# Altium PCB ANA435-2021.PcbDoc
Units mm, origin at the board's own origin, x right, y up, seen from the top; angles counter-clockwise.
Board outline 436.88 x 101.6 mm, 2 copper layers (Top Layer, Bottom Layer); 26 components, 49 nets, 210 pads, 1242 vias.
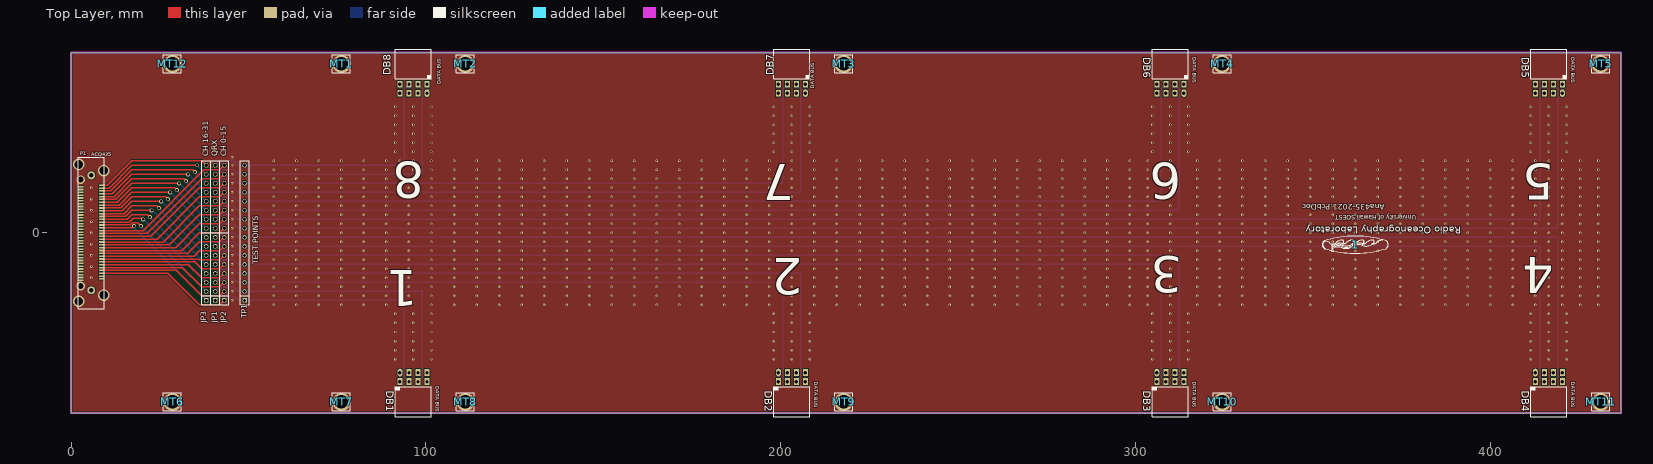
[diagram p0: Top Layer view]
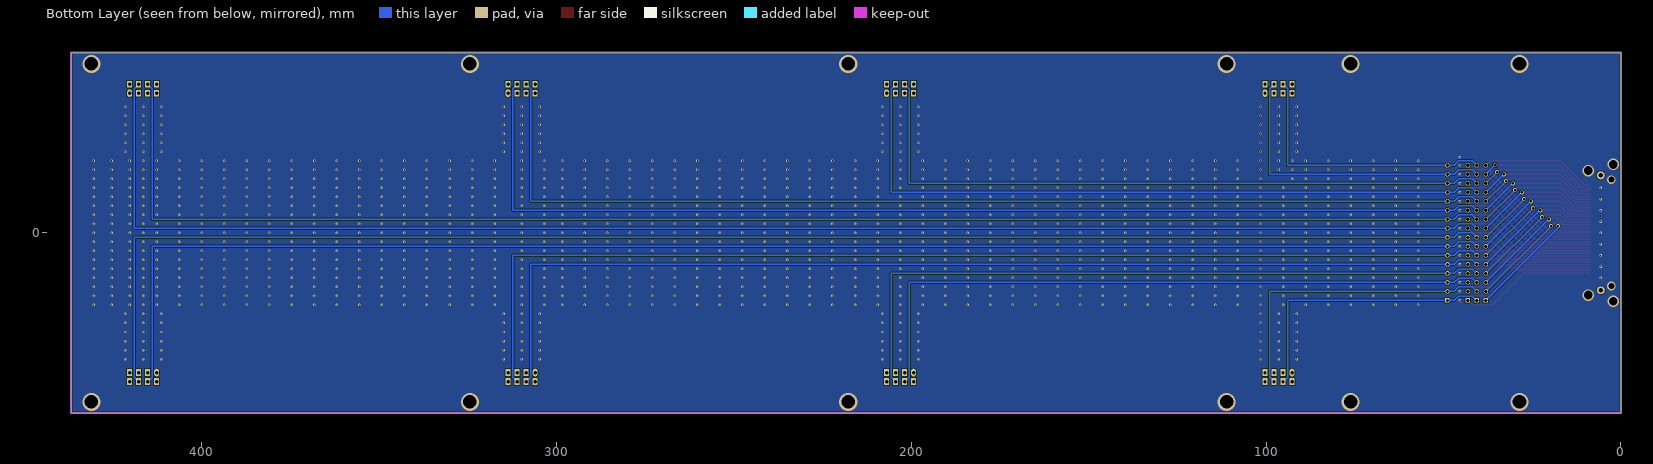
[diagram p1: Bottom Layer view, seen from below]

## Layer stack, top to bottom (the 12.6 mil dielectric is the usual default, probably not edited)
Top Solder: solder mask 0.0102, Solder Resist, Dk 3.5
Top Layer: signal copper 0.0356
Dielectric 1: dielectric 0.32, FR-4, Dk 4.8
Bottom Layer: signal copper 0.0356
Bottom Solder: solder mask 0.0102, Solder Resist, Dk 3.5

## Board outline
0,-50.8 436.88,-50.8 436.88,50.8 0,50.8

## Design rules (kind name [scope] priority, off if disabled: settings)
Clearance [All] p1: gap=0.203 ignorepadtopadclearanceinfootprint=FALSE
HoleSize [All] p1: absolutevalues=TRUE maxlimit=10 minlimit=0.025 maxpercent=80.000 minpercent=20.000
MinimumSolderMaskSliver [All] p1 off: minsoldermaskwidth=0.254
PlaneClearance PlaneClearance_12 [HasPad('MT9-1')] p1: clearance=1.27
PlaneClearance PlaneClearance_11 [HasPad('MT11-1')] p2: clearance=1.27
PlaneClearance PlaneClearance_10 [HasPad('MT5-1')] p3: clearance=1.27
PlaneClearance PlaneClearance_9 [HasPad('MT4-1')] p4: clearance=1.27
PlaneClearance PlaneClearance_8 [HasPad('MT10-1')] p5: clearance=1.27
PlaneClearance PlaneClearance_7 [HasPad('MT3-1')] p6: clearance=1.27
PlaneClearance PlaneClearance_6 [HasPad('MT12-1')] p7: clearance=1.27
PlaneClearance PlaneClearance_5 [HasPad('MT1-1')] p8: clearance=1.27
PlaneClearance PlaneClearance_4 [HasPad('MT2-1')] p9: clearance=1.27
PlaneClearance PlaneClearance_3 [HasPad('MT8-1')] p10: clearance=1.27
PlaneClearance PlaneClearance_2 [HasPad('MT7-1')] p11: clearance=1.27
PlaneClearance PlaneClearance_1 [HasPad('MT6-1')] p12: clearance=1.27
PlaneClearance [All] p13: clearance=0.254
PolygonConnect [All] p1: thpad.connectstyle=Relief thpad.reliefconductorwidth=0.254 thpad.reliefentries=4 thpad.polygonreliefangle="90 Angle" thpad.airgapwidth=0.203 smdpad.connectstyle=Relief smdpad.reliefconductorwidth=0.254 smdpad.reliefentries=4 smdpad.polygonreliefangle="90 Angle" smdpad.airgapwidth=0.203 via.connectstyle=Direct via.reliefconductorwidth=0.254 via.reliefentries=4 via.polygonreliefangle="90 Angle" via.airgapwidth=0.254
RoutingPriority [All] p1: routingpriority=2
RoutingVias [All] p1: holewidth=0.7 width=1.1 viastyle="Through Hole" minholewidth=0.3 minwidth=0.7 maxholewidth=4 maxwidth=7
SilkToSilkClearance [All] p1 off: silktosilkclearance=0.254
SilkToSolderMaskClearance [IsPad] p1 off: minsilkscreentomaskgap=0.254 clearancetoexposedcopper=TRUE
SolderMaskExpansion [All] p1: expansion=0.051
Width [All] p1: maxlimit=10 minlimit=0.254 preferedwidth=0.254 minimp=50.000000 maximp=50.000000 favimp=50.000000
24 further rules are at their usual default settings.

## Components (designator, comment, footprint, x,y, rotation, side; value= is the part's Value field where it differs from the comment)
1 "" LOGOTINY 361.99,-3.328 r180 top
DB1 "DATA BUS" TSW-4X2F 96.52,-40.64 r180 top
DB2 "DATA BUS" TSW-4X2F 203.2,-40.64 r180 top
DB3 "DATA BUS" TSW-4X2F 309.88,-40.64 r180 top
DB4 "DATA BUS" TSW-4X2F 416.56,-40.64 r180 top
DB5 "DATA BUS" TSW-4X2F 416.56,40.64 r0 top
DB6 "DATA BUS" TSW-4X2F 309.88,40.64 r0 top
DB7 "DATA BUS" TSW-4X2F 203.2,40.64 r0 top
DB8 "DATA BUS" TSW-4X2F 96.52,40.64 r0 top
JP1 "QRX" SIP16 40.64,-19.05 r90 top
JP2 "CH 0-15" SIP16 43.18,-19.05 r90 top
JP3 "CH 16-31" SIP16 38.1,-19.05 r90 top
MT1 "GND" MOUNT-3.5 76.2,47.625 r0 top
MT2 "GND" MOUNT-3.5 111.125,47.625 r0 top
MT3 "GND" MOUNT-3.5 217.805,47.625 r0 top
MT4 "GND" MOUNT-3.5 324.485,47.625 r0 top
MT5 "GND" MOUNT-3.5 431.165,47.625 r0 top
MT6 "GND" MOUNT-3.5 28.575,-47.625 r0 top
MT7 "GND" MOUNT-3.5 76.2,-47.625 r0 top
MT8 "GND" MOUNT-3.5 111.125,-47.625 r0 top
MT9 "GND" MOUNT-3.5 217.805,-47.625 r0 top
MT10 "GND" MOUNT-3.5 324.485,-47.625 r0 top
MT11 "GND" MOUNT-3.5 431.165,-47.625 r0 top
MT12 "GND" MOUNT-3.5 28.575,47.625 r0 top
P1 "ACQ435" VHDCI-SMT 5.69,0.025 r270 top
TP1 "TEST POINTS" SIP16 48.895,-19.05 r90 top

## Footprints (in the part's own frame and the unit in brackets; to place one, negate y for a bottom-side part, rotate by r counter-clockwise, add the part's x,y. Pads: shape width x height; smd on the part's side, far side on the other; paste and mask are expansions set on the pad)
LOGOTINY [mm]
  silkscreen extent -9.29,-2.41 9.29,2.41
MOUNT-3.5 [mm]
  round 5.08 on Mech1: 1(0,0)
  silkscreen extent -2.54,-2.54 2.54,2.54
SIP16 [mil]
  rect 50x50 hole 36: 1(0,0)
  round 50 hole 36: 2(100,0) 3(200,0) 4(300,0) 5(400,0) 6(500,0) 7(600,0) 8(700,0) 9(800,0) 10(900,0) 11(1000,0) 12(1100,0) 13(1200,0) 14(1300,0) 15(1400,0) 16(1500,0)
  silkscreen extent -50,-50 1550,50
TSW-4X2F [mil]
  oval 56x85 hole 38: 1(150,-50)
  rect 56x75 hole 38: 2(150,50) 3(50,-50) 4(50,50) 5(-50,-50) 6(-50,50) 7(-150,-50) 8(-150,50)
  silkscreen extent -200,110 200,440
VHDCI-SMT [mm]
  round 2.25 hole 1.2: 0(16.2,0) 0_1(-16.2,0)
  rect 0.45x1.5 smd: 1(13,3) 2(12.2,3) 3(11.4,3) 4(10.6,3) 5(9.8,3) 6(9,3) 7(8.2,3) 8(7.4,3) 9(6.6,3) 10(5.8,3) 11(5,3) 12(4.2,3) 13(3.4,3) 14(2.6,3) 15(1.8,3) 16(1,3) 17(0.2,3) 18(-0.6,3) 19(-1.4,3) 20(-2.2,3) 21(-3,3) 22(-3.8,3) 23(-4.6,3) 24(-5.4,3) 25(-6.2,3) 26(-7,3) 27(-7.8,3) 28(-8.6,3) 29(-9.4,3) 30(-10.2,3) 31(-11,3) 32(-11.8,3) 33(-12.6,3) 34(-13.4,3) 35(13.4,-3) 36(12.6,-3) 37(11.8,-3) 38(11,-3) 39(10.2,-3) 40(9.4,-3) 41(8.6,-3) 42(7.8,-3) 43(7,-3) 44(6.2,-3) 45(5.4,-3) 46(4.6,-3) 47(3.8,-3) 48(3,-3) 49(2.2,-3) 50(1.4,-3) 51(0.6,-3) 52(-0.2,-3) 53(-1,-3) 54(-1.8,-3) 55(-2.6,-3) 56(-3.4,-3) 57(-4.2,-3) 58(-5,-3) 59(-5.8,-3) 60(-6.6,-3) 61(-7.4,-3) 62(-8.2,-3) 63(-9,-3) 64(-9.8,-3) 65(-10.6,-3) 66(-11.4,-3) 67(-12.2,-3) 68(-13,-3)
  silkscreen extent -21.35,-3.73 21.35,3.73

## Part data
DB1 DB2 DB3 DB4 DB5 DB6 DB7 DB8: library part "HEADER 4X2"
JP1 JP2 JP3 TP1: library part "HEADER 16"
MT1 MT2 MT3 MT4 MT5 MT6 MT7 MT8 MT9 MT10 MT11 MT12: library part TP_1
P1: library part MDR68

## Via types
v1: diameter 0.7, hole 0.3, Top Layer to Bottom Layer, 1209 vias
v2: diameter 1.1, hole 0.7, Top Layer to Bottom Layer, 15 vias
v3: diameter 5.08, hole 3.85, Top Layer to Bottom Layer, 12 vias
v4: diameter 3.24, hole 2.44, Top Layer to Bottom Layer, 4 vias
v5: diameter 2.4, hole 1.75, Top Layer to Bottom Layer, 2 vias

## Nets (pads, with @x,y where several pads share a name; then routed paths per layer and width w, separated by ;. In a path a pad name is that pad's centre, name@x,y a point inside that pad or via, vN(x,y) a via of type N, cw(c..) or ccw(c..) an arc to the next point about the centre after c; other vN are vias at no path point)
ADP0: JP2.1 P1.3 | length 38.7
  Top Layer w0.406: P1.3 27.25,-11.375 36.195,-20.32 41.91,-20.32 JP2.1
ADP1: JP2.2 P1.4 | length 38
  Top Layer w0.406: P1.4 29.625,-10.575 36.83,-17.78 41.91,-17.78 JP2.2
ADP2: JP2.3 P1.5 | length 37.3
  Top Layer w0.406: P1.5 31.365,-9.775 36.83,-15.24 41.91,-15.24 JP2.3
ADP3: JP2.4 P1.6 | length 36.6
  Top Layer w0.406: P1.6 33.105,-8.975 36.83,-12.7 41.91,-12.7 JP2.4
ADP4: JP2.5 P1.7 | length 35.8
  Top Layer w0.406: P1.7 34.845,-8.175 36.83,-10.16 41.91,-10.16 JP2.5
ADP5: JP2.6 P1.8 | length 35.1
  Top Layer w0.406: P1.8 35.95,-7.375 36.195,-7.62 41.91,-7.62 JP2.6
ADP6: JP2.7 P1.9 | length 35.6
  Top Layer w0.406: P1.9 34.7,-6.575 36.195,-5.08 41.91,-5.08 JP2.7
ADP7: JP2.8 P1.10 | length 36.4
  Top Layer w0.406: P1.10 32.96,-5.775 36.195,-2.54 41.91,-2.54 JP2.8
ADP8: JP2.9 P1.11 | length 37.1
  Top Layer w0.406: P1.11 31.22,-4.975 36.195,0 41.91,0 JP2.9
ADP9: JP2.10 P1.12 | length 37.8
  Top Layer w0.406: P1.12 29.48,-4.175 36.195,2.54 41.91,2.54 JP2.10
ADP10: JP2.11 P1.13 | length 38.5
  Top Layer w0.406: P1.13 27.74,-3.375 36.195,5.08 41.91,5.08 JP2.11
ADP11: JP2.12 P1.14 | length 39.2
  Top Layer w0.406: P1.14 26,-2.575 36.195,7.62 41.91,7.62 JP2.12
ADP12: JP2.13 P1.15 | length 40
  Top Layer w0.406: P1.15 24.26,-1.775 36.195,10.16 41.91,10.16 JP2.13
ADP13: JP2.14 P1.16 | length 40.7
  Top Layer w0.406: P1.16 22.52,-0.975 36.195,12.7 41.91,12.7 JP2.14
ADP14: JP2.15 P1.17 | length 41.4
  Top Layer w0.406: P1.17 21.415,-0.175 36.83,15.24 41.91,15.24 JP2.15
ADP15: JP2.16 P1.18 | length 42.1
  Top Layer w0.406: P1.18 20.31,0.625 37.465,17.78 41.91,17.78 JP2.16
ADP16: JP3.1 P1.19 | length 39
  Top Layer w0.406: P1.19 17.3,1.425 17.145,1.581 17.469,1.905 v2(17.78,1.905)
  Bottom Layer w0.406: v2(17.78,1.905) 17.78,1.27 JP3.1
ADP17: JP3.2 P1.20 | length 37.7
  Top Layer w0.406: P1.20 16.748,2.225 17.384,2.861 18.176,2.861 18.18,2.857 18.732,2.857 v2(19.685,1.905)
  Bottom Layer w0.406: v2(19.685,1.905) JP3.2
ADP18: JP3.3 P1.21 | length 37.4
  Top Layer w0.406: P1.21 16.36,3.025 17.462,4.127 20.002,4.127 v2(20.32,3.81)
  Bottom Layer w0.406: v2(20.32,3.81) JP3.3
ADP19: JP3.4 P1.22 | length 36.8
  Top Layer w0.406: P1.22 15.89,3.825 17.145,5.08 21.59,5.08 v2(22.225,4.445)
  Bottom Layer w0.406: v2(22.225,4.445) JP3.4
ADP20: JP3.5 P1.23 | length 36.7
  Top Layer w0.406: P1.23 15.42,4.625 17.145,6.35 22.543,6.35 22.701,6.509 v2(22.701,6.35)
  Bottom Layer w0.406: v2(22.701,6.35) 22.86,6.35 JP3.5
ADP21: JP3.6 P1.24 | length 36.1
  Top Layer w0.406: P1.24 14.95,5.425 17.145,7.62 24.13,7.62 v2(24.765,6.985)
  Bottom Layer w0.406: v2(24.765,6.985) JP3.6
ADP22: JP3.7 P1.25 | length 35.8
  Top Layer w0.406: P1.25 14.48,6.225 17.145,8.89 v2(25.4,8.89)
  Bottom Layer w0.406: v2(25.4,8.89) JP3.7
ADP23: JP3.8 P1.26 | length 35.4
  Top Layer w0.406: P1.26 14.01,7.025 17.145,10.16 26.67,10.16 v2(27.305,9.525)
  Bottom Layer w0.406: v2(27.305,9.525) JP3.8
ADP24: JP3.9 P1.27 | length 35.1
  Top Layer w0.406: P1.27 13.54,7.825 17.145,11.43 v2(27.94,11.43)
  Bottom Layer w0.406: v2(27.94,11.43) JP3.9
ADP25: JP3.10 P1.28 | length 34.8
  Top Layer w0.406: P1.28 13.07,8.625 17.145,12.7 29.21,12.7 v2(29.845,12.065)
  Bottom Layer w0.406: v2(29.845,12.065) JP3.10
ADP26: JP3.11 P1.29 | length 34.4
  Top Layer w0.406: P1.29 12.6,9.425 17.145,13.97 v2(30.48,13.97)
  Bottom Layer w0.406: v2(30.48,13.97) JP3.11
ADP27: JP3.12 P1.30 | length 34.1
  Top Layer w0.406: P1.30 12.13,10.225 17.145,15.24 31.75,15.24 v2(32.385,14.605)
  Bottom Layer w0.406: v2(32.385,14.605) JP3.12
ADP28: JP3.13 P1.31 | length 33.8
  Top Layer w0.406: P1.31 11.66,11.025 17.145,16.51 v2(33.02,16.51)
  Bottom Layer w0.406: v2(33.02,16.51) JP3.13
ADP29: JP3.14 P1.32 | length 33.5
  Top Layer w0.406: P1.32 11.19,11.825 17.145,17.78 34.29,17.78 v2(34.925,17.145)
  Bottom Layer w0.406: v2(34.925,17.145) JP3.14
ADP30: JP3.15 P1.33 | length 33.1
  Top Layer w0.406: P1.33 10.72,12.625 17.145,19.05 v2(35.56,19.05)
  Bottom Layer w0.406: v2(35.56,19.05) JP3.15
ADP31: JP3.16 P1.34 | length 32.8
  Top Layer w0.406: P1.34 10.25,13.425 17.145,20.32 36.83,20.32 JP3.16
GND: DB1.1 DB1.2 DB1.3 DB1.5 DB1.7 DB1.8 DB2.1 DB2.2 DB2.3 DB2.5 DB2.7 DB2.8 DB3.1 DB3.2 DB3.3 DB3.5 DB3.7 DB3.8 DB4.1 DB4.2 DB4.3 DB4.5 DB4.7 DB4.8 DB5.1 DB5.2 DB5.3 DB5.5 DB5.7 DB5.8 DB6.1 DB6.2 DB6.3 DB6.5 DB6.7 DB6.8 DB7.1 DB7.2 DB7.3 DB7.5 DB7.7 DB7.8 DB8.1 DB8.2 DB8.3 DB8.5 DB8.7 DB8.8 P1.0 P1.0_1 P1.1 P1.2 P1.35 P1.36 P1.37 P1.38 P1.39 P1.40 P1.41 P1.42 P1.43 P1.44 P1.45 P1.46 P1.47 P1.48 P1.49 P1.50 P1.51 P1.52 P1.53 P1.54 P1.55 P1.56 P1.57 P1.58 P1.59 P1.60 P1.61 P1.62 P1.63 P1.64 P1.65 P1.66 P1.67 P1.68
  other v1: 91.44,-35.56 96.52,-35.56 101.6,-35.56 198.12,-35.56 203.2,-35.56 208.28,-35.56 304.8,-35.56 309.88,-35.56 314.96,-35.56 411.48,-35.56 416.56,-35.56 421.64,-35.56 91.44,-33.02 96.52,-33.02 101.6,-33.02 198.12,-33.02 203.2,-33.02 208.28,-33.02 304.8,-33.02 309.88,-33.02 314.96,-33.02 411.48,-33.02 416.56,-33.02 421.64,-33.02 91.44,-30.48 96.52,-30.48 101.6,-30.48 198.12,-30.48 203.2,-30.48 208.28,-30.48 304.8,-30.48 309.88,-30.48 314.96,-30.48 411.48,-30.48 416.56,-30.48 421.64,-30.48 91.44,-27.94 96.52,-27.94 101.6,-27.94 198.12,-27.94 203.2,-27.94 208.28,-27.94 304.8,-27.94 309.88,-27.94 314.96,-27.94 411.48,-27.94 416.56,-27.94 421.64,-27.94 91.44,-25.4 96.52,-25.4 101.6,-25.4 198.12,-25.4 203.2,-25.4 208.28,-25.4 304.8,-25.4 309.88,-25.4 314.96,-25.4 411.48,-25.4 416.56,-25.4 421.64,-25.4 91.44,-22.86 96.52,-22.86 101.6,-22.86 198.12,-22.86 203.2,-22.86 208.28,-22.86 304.8,-22.86 309.88,-22.86 314.96,-22.86 411.48,-22.86 416.56,-22.86 421.64,-22.86 57.15,-20.32 63.5,-20.32 69.85,-20.32 76.2,-20.32 82.55,-20.32 88.9,-20.32 95.25,-20.32 101.6,-20.32 107.95,-20.32 114.3,-20.32 120.65,-20.32 127,-20.32 133.35,-20.32 139.7,-20.32 146.05,-20.32 152.4,-20.32 158.75,-20.32 165.1,-20.32 171.45,-20.32 177.8,-20.32 184.15,-20.32 190.5,-20.32 196.85,-20.32 203.2,-20.32 209.55,-20.32 215.9,-20.32 222.25,-20.32 228.6,-20.32 234.95,-20.32 241.3,-20.32 247.65,-20.32 254,-20.32 260.35,-20.32 266.7,-20.32 273.05,-20.32 279.4,-20.32 285.75,-20.32 292.1,-20.32 298.45,-20.32 303.53,-20.32 309.88,-20.32 317.5,-20.32 323.85,-20.32 330.2,-20.32 336.55,-20.32 342.9,-20.32 349.25,-20.32 355.6,-20.32 361.95,-20.32 368.3,-20.32 374.65,-20.32 381,-20.32 387.35,-20.32 393.7,-20.32 400.05,-20.32 406.4,-20.32 412.75,-20.32 416.56,-20.32 420.37,-20.32 425.45,-20.32 430.53,-20.32 45.402,-19.05 57.15,-17.78 63.5,-17.78 69.85,-17.78 76.2,-17.78 82.55,-17.78 88.9,-17.78 95.25,-17.78 101.6,-17.78 107.95,-17.78 114.3,-17.78 120.65,-17.78 127,-17.78 133.35,-17.78 139.7,-17.78 146.05,-17.78 152.4,-17.78 158.75,-17.78 165.1,-17.78 171.45,-17.78 177.8,-17.78 184.15,-17.78 190.5,-17.78 196.85,-17.78 203.2,-17.78 209.55,-17.78 215.9,-17.78 222.25,-17.78 228.6,-17.78 234.95,-17.78 241.3,-17.78 247.65,-17.78 254,-17.78 260.35,-17.78 266.7,-17.78 273.05,-17.78 279.4,-17.78 285.75,-17.78 292.1,-17.78 298.45,-17.78 303.53,-17.78 309.88,-17.78 317.5,-17.78 323.85,-17.78 330.2,-17.78 336.55,-17.78 342.9,-17.78 349.25,-17.78 355.6,-17.78 361.95,-17.78 368.3,-17.78 374.65,-17.78 381,-17.78 387.35,-17.78 393.7,-17.78 400.05,-17.78 406.4,-17.78 412.75,-17.78 416.56,-17.78 420.37,-17.78 425.45,-17.78 430.53,-17.78 45.402,-16.51 57.15,-15.24 63.5,-15.24 69.85,-15.24 76.2,-15.24 82.55,-15.24 88.9,-15.24 95.25,-15.24 101.6,-15.24 107.95,-15.24 114.3,-15.24 120.65,-15.24 127,-15.24 133.35,-15.24 139.7,-15.24 146.05,-15.24 152.4,-15.24 158.75,-15.24 165.1,-15.24 171.45,-15.24 177.8,-15.24 184.15,-15.24 190.5,-15.24 196.85,-15.24 203.2,-15.24 209.55,-15.24 215.9,-15.24 222.25,-15.24 228.6,-15.24 234.95,-15.24 241.3,-15.24 247.65,-15.24 254,-15.24 260.35,-15.24 266.7,-15.24 273.05,-15.24 279.4,-15.24 285.75,-15.24 292.1,-15.24 298.45,-15.24 303.53,-15.24 309.88,-15.24 317.5,-15.24 323.85,-15.24 330.2,-15.24 336.55,-15.24 342.9,-15.24 349.25,-15.24 355.6,-15.24 361.95,-15.24 368.3,-15.24 374.65,-15.24 381,-15.24 387.35,-15.24 393.7,-15.24 400.05,-15.24 406.4,-15.24 412.75,-15.24 416.56,-15.24 420.37,-15.24 425.45,-15.24 430.53,-15.24 45.402,-13.97 5.715,-12.7 57.15,-12.7 63.5,-12.7 69.85,-12.7 76.2,-12.7 82.55,-12.7 88.9,-12.7 95.25,-12.7 101.6,-12.7 107.95,-12.7 114.3,-12.7 120.65,-12.7 127,-12.7 133.35,-12.7 139.7,-12.7 146.05,-12.7 152.4,-12.7 158.75,-12.7 165.1,-12.7 171.45,-12.7 177.8,-12.7 184.15,-12.7 190.5,-12.7 196.85,-12.7 203.2,-12.7 209.55,-12.7 215.9,-12.7 222.25,-12.7 228.6,-12.7 234.95,-12.7 241.3,-12.7 247.65,-12.7 254,-12.7 260.35,-12.7 266.7,-12.7 273.05,-12.7 279.4,-12.7 285.75,-12.7 292.1,-12.7 298.45,-12.7 303.53,-12.7 309.88,-12.7 317.5,-12.7 323.85,-12.7 330.2,-12.7 336.55,-12.7 342.9,-12.7 349.25,-12.7 355.6,-12.7 361.95,-12.7 368.3,-12.7 374.65,-12.7 381,-12.7 387.35,-12.7 393.7,-12.7 400.05,-12.7 406.4,-12.7 412.75,-12.7 416.56,-12.7 420.37,-12.7 425.45,-12.7 430.53,-12.7 45.402,-11.43 57.15,-10.16 63.5,-10.16 69.85,-10.16 76.2,-10.16 82.55,-10.16 88.9,-10.16 95.25,-10.16 101.6,-10.16 107.95,-10.16 114.3,-10.16 120.65,-10.16 127,-10.16 133.35,-10.16 139.7,-10.16 146.05,-10.16 152.4,-10.16 158.75,-10.16 165.1,-10.16 171.45,-10.16 177.8,-10.16 184.15,-10.16 190.5,-10.16 196.85,-10.16 203.2,-10.16 209.55,-10.16 215.9,-10.16 222.25,-10.16 228.6,-10.16 234.95,-10.16 241.3,-10.16 247.65,-10.16 254,-10.16 260.35,-10.16 266.7,-10.16 273.05,-10.16 279.4,-10.16 285.75,-10.16 292.1,-10.16 298.45,-10.16 303.53,-10.16 309.88,-10.16 317.5,-10.16 323.85,-10.16 330.2,-10.16 336.55,-10.16 342.9,-10.16 349.25,-10.16 355.6,-10.16 361.95,-10.16 368.3,-10.16 374.65,-10.16 381,-10.16 387.35,-10.16 393.7,-10.16 400.05,-10.16 406.4,-10.16 412.75,-10.16 416.56,-10.16 420.37,-10.16 425.45,-10.16 430.53,-10.16 5.715,-9.525 45.402,-8.89 57.15,-7.62 63.5,-7.62 69.85,-7.62 76.2,-7.62 82.55,-7.62 88.9,-7.62 95.25,-7.62 101.6,-7.62 107.95,-7.62 114.3,-7.62 120.65,-7.62 127,-7.62 133.35,-7.62 139.7,-7.62 146.05,-7.62 152.4,-7.62 158.75,-7.62 165.1,-7.62 171.45,-7.62 177.8,-7.62 184.15,-7.62 190.5,-7.62 196.85,-7.62 203.2,-7.62 209.55,-7.62 215.9,-7.62 222.25,-7.62 228.6,-7.62 234.95,-7.62 241.3,-7.62 247.65,-7.62 254,-7.62 260.35,-7.62 266.7,-7.62 273.05,-7.62 279.4,-7.62 285.75,-7.62 292.1,-7.62 298.45,-7.62 303.53,-7.62 309.88,-7.62 317.5,-7.62 323.85,-7.62 330.2,-7.62 336.55,-7.62 342.9,-7.62 349.25,-7.62 355.6,-7.62 361.95,-7.62 368.3,-7.62 374.65,-7.62 381,-7.62 387.35,-7.62 393.7,-7.62 400.05,-7.62 406.4,-7.62 412.75,-7.62 416.56,-7.62 420.37,-7.62 425.45,-7.62 430.53,-7.62 5.715,-6.35 45.402,-6.35 57.15,-5.08 63.5,-5.08 69.85,-5.08 76.2,-5.08 82.55,-5.08 88.9,-5.08 95.25,-5.08 101.6,-5.08 107.95,-5.08 114.3,-5.08 120.65,-5.08 127,-5.08 133.35,-5.08 139.7,-5.08 146.05,-5.08 152.4,-5.08 158.75,-5.08 165.1,-5.08 171.45,-5.08 177.8,-5.08 184.15,-5.08 190.5,-5.08 196.85,-5.08 203.2,-5.08 209.55,-5.08 215.9,-5.08 222.25,-5.08 228.6,-5.08 234.95,-5.08 241.3,-5.08 247.65,-5.08 254,-5.08 260.35,-5.08 266.7,-5.08 273.05,-5.08 279.4,-5.08 285.75,-5.08 292.1,-5.08 298.45,-5.08 303.53,-5.08 309.88,-5.08 317.5,-5.08 323.85,-5.08 330.2,-5.08 336.55,-5.08 342.9,-5.08 349.25,-5.08 355.6,-5.08 361.95,-5.08 368.3,-5.08 374.65,-5.08 381,-5.08 387.35,-5.08 393.7,-5.08 400.05,-5.08 406.4,-5.08 412.75,-5.08 416.56,-5.08 420.37,-5.08 425.45,-5.08 430.53,-5.08 45.402,-3.81 5.715,-3.175 57.15,-2.54 63.5,-2.54 69.85,-2.54 76.2,-2.54 82.55,-2.54 88.9,-2.54 95.25,-2.54 101.6,-2.54 107.95,-2.54 114.3,-2.54 120.65,-2.54 127,-2.54 133.35,-2.54 139.7,-2.54 146.05,-2.54 152.4,-2.54 158.75,-2.54 165.1,-2.54 171.45,-2.54 177.8,-2.54 184.15,-2.54 190.5,-2.54 196.85,-2.54 203.2,-2.54 209.55,-2.54 215.9,-2.54 222.25,-2.54 228.6,-2.54 234.95,-2.54 241.3,-2.54 247.65,-2.54 254,-2.54 260.35,-2.54 266.7,-2.54 273.05,-2.54 279.4,-2.54 285.75,-2.54 292.1,-2.54 298.45,-2.54 303.53,-2.54 309.88,-2.54 317.5,-2.54 323.85,-2.54 330.2,-2.54 336.55,-2.54 342.9,-2.54 349.25,-2.54 355.6,-2.54 361.95,-2.54 368.3,-2.54 374.65,-2.54 381,-2.54 387.35,-2.54 393.7,-2.54 400.05,-2.54 406.4,-2.54 412.75,-2.54 416.56,-2.54 420.37,-2.54 425.45,-2.54 430.53,-2.54 45.402,-1.27 5.715,0 57.15,0 63.5,0 69.85,0 76.2,0 82.55,0 88.9,0 95.25,0 101.6,0 107.95,0 114.3,0 120.65,0 127,0 133.35,0 139.7,0 146.05,0 152.4,0 158.75,0 165.1,0 171.45,0 177.8,0 184.15,0 190.5,0 196.85,0 203.2,0 209.55,0 215.9,0 222.25,0 228.6,0 234.95,0 241.3,0 247.65,0 254,0 260.35,0 266.7,0 273.05,0 279.4,0 285.75,0 292.1,0 298.45,0 303.53,0 309.88,0 317.5,0 323.85,0 330.2,0 336.55,0 342.9,0 349.25,0 355.6,0 361.95,0 368.3,0 374.65,0 381,0 387.35,0 393.7,0 400.05,0 406.4,0 412.75,0 416.56,0 420.37,0 425.45,0 430.53,0 45.402,1.27 57.15,2.54 63.5,2.54 69.85,2.54 76.2,2.54 82.55,2.54 88.9,2.54 95.25,2.54 101.6,2.54 107.95,2.54 114.3,2.54 120.65,2.54 127,2.54 133.35,2.54 139.7,2.54 146.05,2.54 152.4,2.54 158.75,2.54 165.1,2.54 171.45,2.54 177.8,2.54 184.15,2.54 190.5,2.54 196.85,2.54 203.2,2.54 209.55,2.54 215.9,2.54 222.25,2.54 228.6,2.54 234.95,2.54 241.3,2.54 247.65,2.54 254,2.54 260.35,2.54 266.7,2.54 273.05,2.54 279.4,2.54 285.75,2.54 292.1,2.54 298.45,2.54 303.53,2.54 309.88,2.54 317.5,2.54 323.85,2.54 330.2,2.54 336.55,2.54 342.9,2.54 349.25,2.54 355.6,2.54 361.95,2.54 368.3,2.54 374.65,2.54 381,2.54 387.35,2.54 393.7,2.54 400.05,2.54 406.4,2.54 412.75,2.54 416.56,2.54 420.37,2.54 425.45,2.54 430.53,2.54 5.715,3.175 45.402,3.81 57.15,5.08 63.5,5.08 69.85,5.08 76.2,5.08 82.55,5.08 88.9,5.08 95.25,5.08 101.6,5.08 107.95,5.08 114.3,5.08 120.65,5.08 127,5.08 133.35,5.08 139.7,5.08 146.05,5.08 152.4,5.08 158.75,5.08 165.1,5.08 171.45,5.08 177.8,5.08 184.15,5.08 190.5,5.08 196.85,5.08 203.2,5.08 209.55,5.08 215.9,5.08 222.25,5.08 228.6,5.08 234.95,5.08 241.3,5.08 247.65,5.08 254,5.08 260.35,5.08 266.7,5.08 273.05,5.08 279.4,5.08 285.75,5.08 292.1,5.08 298.45,5.08 303.53,5.08 309.88,5.08 317.5,5.08 323.85,5.08 330.2,5.08 336.55,5.08 342.9,5.08 349.25,5.08 355.6,5.08 361.95,5.08 368.3,5.08 374.65,5.08 381,5.08 387.35,5.08 393.7,5.08 400.05,5.08 406.4,5.08 412.75,5.08 416.56,5.08 420.37,5.08 425.45,5.08 430.53,5.08 5.715,6.35 45.402,6.35 57.15,7.62 63.5,7.62 69.85,7.62 76.2,7.62 82.55,7.62 88.9,7.62 95.25,7.62 101.6,7.62 107.95,7.62 114.3,7.62 120.65,7.62 127,7.62 133.35,7.62 139.7,7.62 146.05,7.62 152.4,7.62 158.75,7.62 165.1,7.62 171.45,7.62 177.8,7.62 184.15,7.62 190.5,7.62 196.85,7.62 203.2,7.62 209.55,7.62 215.9,7.62 222.25,7.62 228.6,7.62 234.95,7.62 241.3,7.62 247.65,7.62 254,7.62 260.35,7.62 266.7,7.62 273.05,7.62 279.4,7.62 285.75,7.62 292.1,7.62 298.45,7.62 303.53,7.62 309.88,7.62 317.5,7.62 323.85,7.62 330.2,7.62 336.55,7.62 342.9,7.62 349.25,7.62 355.6,7.62 361.95,7.62 368.3,7.62 374.65,7.62 381,7.62 387.35,7.62 393.7,7.62 400.05,7.62 406.4,7.62 412.75,7.62 416.56,7.62 420.37,7.62 425.45,7.62 430.53,7.62 45.402,8.89 5.715,9.525 57.15,10.16 63.5,10.16 69.85,10.16 76.2,10.16 82.55,10.16 88.9,10.16 95.25,10.16 101.6,10.16 107.95,10.16 114.3,10.16 120.65,10.16 127,10.16 133.35,10.16 139.7,10.16 146.05,10.16 152.4,10.16 158.75,10.16 165.1,10.16 171.45,10.16 177.8,10.16 184.15,10.16 190.5,10.16 196.85,10.16 203.2,10.16 209.55,10.16 215.9,10.16 222.25,10.16 228.6,10.16 234.95,10.16 241.3,10.16 247.65,10.16 254,10.16 260.35,10.16 266.7,10.16 273.05,10.16 279.4,10.16 285.75,10.16 292.1,10.16 298.45,10.16 303.53,10.16 309.88,10.16 317.5,10.16 323.85,10.16 330.2,10.16 336.55,10.16 342.9,10.16 349.25,10.16 355.6,10.16 361.95,10.16 368.3,10.16 374.65,10.16 381,10.16 387.35,10.16 393.7,10.16 400.05,10.16 406.4,10.16 412.75,10.16 416.56,10.16 420.37,10.16 425.45,10.16 430.53,10.16 45.402,11.43 5.715,12.7 57.15,12.7 63.5,12.7 69.85,12.7 76.2,12.7 82.55,12.7 88.9,12.7 95.25,12.7 101.6,12.7 107.95,12.7 114.3,12.7 120.65,12.7 127,12.7 133.35,12.7 139.7,12.7 146.05,12.7 152.4,12.7 158.75,12.7 165.1,12.7 171.45,12.7 177.8,12.7 184.15,12.7 190.5,12.7 196.85,12.7 203.2,12.7 209.55,12.7 215.9,12.7 222.25,12.7 228.6,12.7 234.95,12.7 241.3,12.7 247.65,12.7 254,12.7 260.35,12.7 266.7,12.7 273.05,12.7 279.4,12.7 285.75,12.7 292.1,12.7 298.45,12.7 303.53,12.7 309.88,12.7 317.5,12.7 323.85,12.7 330.2,12.7 336.55,12.7 342.9,12.7 349.25,12.7 355.6,12.7 361.95,12.7 368.3,12.7 374.65,12.7 381,12.7 387.35,12.7 393.7,12.7 400.05,12.7 406.4,12.7 412.75,12.7 416.56,12.7 420.37,12.7 425.45,12.7 430.53,12.7 45.402,13.97 57.15,15.24 63.5,15.24 69.85,15.24 76.2,15.24 82.55,15.24 88.9,15.24 92.71,15.24 101.6,15.24 107.95,15.24 114.3,15.24 120.65,15.24 127,15.24 133.35,15.24 139.7,15.24 146.05,15.24 152.4,15.24 158.75,15.24 165.1,15.24 171.45,15.24 177.8,15.24 184.15,15.24 190.5,15.24 196.85,15.24 203.2,15.24 209.55,15.24 215.9,15.24 222.25,15.24 228.6,15.24 234.95,15.24 241.3,15.24 247.65,15.24 254,15.24 260.35,15.24 266.7,15.24 273.05,15.24 279.4,15.24 285.75,15.24 292.1,15.24 298.45,15.24 303.53,15.24 309.88,15.24 317.5,15.24 323.85,15.24 330.2,15.24 336.55,15.24 342.9,15.24 349.25,15.24 355.6,15.24 361.95,15.24 368.3,15.24 374.65,15.24 381,15.24 387.35,15.24 393.7,15.24 400.05,15.24 406.4,15.24 412.75,15.24 416.56,15.24 420.37,15.24 425.45,15.24 430.53,15.24 45.402,16.51 57.15,17.78 63.5,17.78 69.85,17.78 76.2,17.78 82.55,17.78 88.9,17.78 92.71,17.78 96.52,17.78 101.6,17.78 107.95,17.78 114.3,17.78 120.65,17.78 127,17.78 133.35,17.78 139.7,17.78 146.05,17.78 152.4,17.78 158.75,17.78 165.1,17.78 171.45,17.78 177.8,17.78 184.15,17.78 190.5,17.78 196.85,17.78 203.2,17.78 209.55,17.78 215.9,17.78 222.25,17.78 228.6,17.78 234.95,17.78 241.3,17.78 247.65,17.78 254,17.78 260.35,17.78 266.7,17.78 273.05,17.78 279.4,17.78 285.75,17.78 292.1,17.78 298.45,17.78 303.53,17.78 309.88,17.78 317.5,17.78 323.85,17.78 330.2,17.78 336.55,17.78 342.9,17.78 349.25,17.78 355.6,17.78 361.95,17.78 368.3,17.78 374.65,17.78 381,17.78 387.35,17.78 393.7,17.78 400.05,17.78 406.4,17.78 412.75,17.78 416.56,17.78 420.37,17.78 425.45,17.78 430.53,17.78 45.402,19.05 57.15,20.32 63.5,20.32 69.85,20.32 76.2,20.32 82.55,20.32 88.9,20.32 92.71,20.32 96.52,20.32 101.6,20.32 107.95,20.32 114.3,20.32 120.65,20.32 127,20.32 133.35,20.32 139.7,20.32 146.05,20.32 152.4,20.32 158.75,20.32 165.1,20.32 171.45,20.32 177.8,20.32 184.15,20.32 190.5,20.32 196.85,20.32 203.2,20.32 209.55,20.32 215.9,20.32 222.25,20.32 228.6,20.32 234.95,20.32 241.3,20.32 247.65,20.32 254,20.32 260.35,20.32 266.7,20.32 273.05,20.32 279.4,20.32 285.75,20.32 292.1,20.32 298.45,20.32 303.53,20.32 309.88,20.32 317.5,20.32 323.85,20.32 330.2,20.32 336.55,20.32 342.9,20.32 349.25,20.32 355.6,20.32 361.95,20.32 368.3,20.32 374.65,20.32 381,20.32 387.35,20.32 393.7,20.32 400.05,20.32 406.4,20.32 412.75,20.32 416.56,20.32 420.37,20.32 425.45,20.32 430.53,20.32 45.402,21.273 91.44,22.86 96.52,22.86 101.6,22.86 198.12,22.86 203.2,22.86 208.28,22.86 304.8,22.86 309.88,22.86 314.96,22.86 411.48,22.86 416.56,22.86 421.64,22.86 91.44,25.4 96.52,25.4 101.6,25.4 198.12,25.4 203.2,25.4 208.28,25.4 304.8,25.4 309.88,25.4 314.96,25.4 411.48,25.4 416.56,25.4 421.64,25.4 91.44,27.94 96.52,27.94 101.6,27.94 198.12,27.94 203.2,27.94 208.28,27.94 304.8,27.94 309.88,27.94 314.96,27.94 411.48,27.94 416.56,27.94 421.64,27.94 91.44,30.48 96.52,30.48 101.6,30.48 198.12,30.48 203.2,30.48 208.28,30.48 304.8,30.48 309.88,30.48 314.96,30.48 411.48,30.48 416.56,30.48 421.64,30.48 91.44,33.02 96.52,33.02 101.6,33.02 198.12,33.02 203.2,33.02 208.28,33.02 304.8,33.02 309.88,33.02 314.96,33.02 411.48,33.02 416.56,33.02 421.64,33.02 91.44,35.56 96.52,35.56 101.6,35.56 198.12,35.56 203.2,35.56 208.28,35.56 304.8,35.56 309.88,35.56 314.96,35.56 411.48,35.56 416.56,35.56 421.64,35.56
  other v3: 28.575,-47.625 76.2,-47.625 111.125,-47.625 217.805,-47.625 324.485,-47.625 431.165,-47.625 28.575,47.625 76.2,47.625 111.125,47.625 217.805,47.625 324.485,47.625 431.165,47.625
  other v4: 2.14,-19.245 9.24,-17.515 9.24,17.565 2.14,19.295
  other v5: 2.69,-14.975 2.69,15.025
I1: DB1.4 JP1.1 TP1.1 | length 77.7
  Bottom Layer w0.4: JP1.1 41.885,-17.805 45.745,-17.805 46.964,-19.024
  Bottom Layer w0.406: 46.964,-19.024 93.98,-19.05 93.98,-40.64 DB1.4
I2: DB2.4 JP1.3 TP1.3 | length 189.5
  Bottom Layer w0.4: JP1.3 41.885,-12.725 45.745,-12.725 46.964,-13.944 ; TP1.3 200.6,-13.97 200.66,-14.03
  Bottom Layer w0.406: 46.964,-13.944 TP1.3@48.895,-13.945 ; 200.66,-14.03 200.66,-40.64 DB2.4
I3: DB3.4 JP1.5 TP1.5 | length 301.3
  Bottom Layer w0.4: JP1.5 41.885,-7.645 45.745,-7.645 46.964,-8.864 ; TP1.5 307.34,-8.89
  Bottom Layer w0.406: 46.964,-8.864 TP1.5@48.895,-8.865 ; 307.34,-8.89 307.34,-40.64 DB3.4
I4: DB4.4 JP1.7 TP1.7 | length 413.2
  Bottom Layer w0.4: JP1.7 41.885,-2.565 45.745,-2.565 46.964,-3.784
  Bottom Layer w0.406: 46.964,-3.784 48.895,-3.785 TP1.7@49.04,-3.639 ; TP1.7 414.02,-3.81 414.02,-40.64 DB4.4
I5: DB5.4 JP1.9 TP1.9 | length 420.9
  Bottom Layer w0.4: JP1.9 41.885,2.515 45.745,2.515 46.964,1.296 ; TP1.9 419.1,1.27
  Bottom Layer w0.406: 46.964,1.296 48.895,1.295 TP1.9@49.04,1.44 ; DB5.4 419.1,40.64 419.1,1.27
I6: DB6.4 JP1.11 TP1.11 | length 308.9
  Bottom Layer w0.4: JP1.11 41.885,7.595 45.745,7.595 46.964,6.376 ; TP1.11 312.42,6.35
  Bottom Layer w0.406: 46.964,6.376 TP1.11@48.895,6.375 ; DB6.4 312.42,40.64 312.42,6.35
I7: DB7.4 JP1.13 TP1.13 | length 197.1
  Bottom Layer w0.4: JP1.13 41.885,12.675 45.745,12.675 46.99,11.43 205.74,11.43
  Bottom Layer w0.406: DB7.4 205.74,40.64 205.74,11.43
I8: DB8.4 JP1.15 TP1.15 | length 85.4
  Bottom Layer w0.4: JP1.15 41.885,17.755 45.745,17.755 46.964,16.536
  Bottom Layer w0.406: 46.964,16.536 48.895,16.535 48.92,16.511 99.059,16.511 99.06,40.64 DB8.4
Q1: DB1.6 JP1.2 TP1.2 | length 85.4
  Bottom Layer w0.406: JP1.2 41.91,-15.24 45.72,-15.24 46.99,-16.51 TP1.2 99.06,-16.51 99.06,-40.64 DB1.6
Q2: DB2.6 JP1.4 TP1.4 | length 197.1
  Bottom Layer w0.4: JP1.4 41.885,-10.185 45.745,-10.185 46.964,-11.404
  Bottom Layer w0.406: 46.964,-11.404 TP1.4@48.895,-11.405 ; TP1.4 205.677,-11.43 205.74,-11.493 205.74,-40.64 DB2.6
Q3: DB3.6 JP1.6 TP1.6 | length 308.9
  Bottom Layer w0.4: JP1.6 41.885,-5.105 45.745,-5.105 46.964,-6.324 ; TP1.6 312.42,-6.35
  Bottom Layer w0.406: 46.964,-6.324 TP1.6@48.895,-6.325 ; DB3.6 312.42,-40.64 312.42,-6.35
Q4: DB4.6 JP1.8 TP1.8 | length 420.6
  Bottom Layer w0.4: JP1.8 41.885,-0.025 45.745,-0.025 46.964,-1.244
  Bottom Layer w0.406: 46.964,-1.244 TP1.8@48.895,-1.245 ; TP1.8 419.1,-1.27 419.1,-40.64 DB4.6
Q5: DB5.6 JP1.10 TP1.10 | length 413.2
  Bottom Layer w0.4: JP1.10 41.885,5.055 45.745,5.055 46.964,3.836 ; TP1.10 414.02,3.81
  Bottom Layer w0.406: 46.964,3.836 48.895,3.835 TP1.10@49.04,3.981 ; 414.02,3.81 414.02,40.64 DB5.6
Q6: DB6.6 JP1.12 TP1.12 | length 301.3
  Bottom Layer w0.4: JP1.12 41.885,10.135 45.745,10.135 46.964,8.916
  Bottom Layer w0.406: 46.964,8.916 TP1.12@48.895,8.915 ; TP1.12 307.34,8.89 307.34,40.64 DB6.6
Q7: DB7.6 JP1.14 TP1.14 | length 189.5
  Bottom Layer w0.4: JP1.14 41.885,15.215 45.745,15.215 46.964,13.996 ; TP1.14 200.66,13.97
  Bottom Layer w0.406: 46.964,13.996 TP1.14@48.895,13.995 ; 200.66,13.97 200.66,40.64 DB7.6
Q8: DB8.6 JP1.16 TP1.16 | length 77.7
  Bottom Layer w0.4: JP1.16 41.885,20.295 45.745,20.295 46.964,19.076
  Bottom Layer w0.406: 46.964,19.076 93.98,19.05 93.98,40.64 DB8.6
pads on no net: MT1.1 MT2.1 MT3.1 MT4.1 MT5.1 MT6.1 MT7.1 MT8.1 MT9.1 MT10.1 MT11.1 MT12.1

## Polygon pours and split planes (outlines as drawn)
GND on Top Layer "Bottom Layer-No Net" (solid, remove dead copper, pour order 0): -4.298,54.219 -4.298,-54.952 -4.543,-55.196 439.225,-55.196 439.469,-54.952 439.469,51.044 441.667,53.242
GND on Bottom Layer "Bottom Layer-No Net" (solid, remove dead copper, pour order 2): -4.298,54.219 -4.298,-54.952 -4.543,-55.196 439.225,-55.196 439.469,-54.952 439.469,51.044 441.667,53.242

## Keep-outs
Keep-Out Layer:
  the board outline again, w0.61

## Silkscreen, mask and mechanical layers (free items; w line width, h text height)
Top Overlay:
  lines w0.305: 36.83,0 44.45,0
  text "8" at 99.5,20.027 h10.16 r180
  text "6" at 312.957,19.783 h10.16 r180
  text "5" at 417.977,19.538 h10.16 r180
  text "7" at 203.786,19.294 h10.16 r180
  text "Ana435-2021.PcbDoc" at 370.245,8.102 h1.52 r180
  text "University of Hawaii SOEST" at 379.135,4.927 h1.27 r180
  text "Radio Oceanography Laboratory" at 391.835,1.752 h1.91 r180
  text "3" at 313.202,-6.594 h10.16 r180
  text "4" at 417.977,-6.838 h10.16 r180
  text "2" at 206.229,-7.083 h10.16 r180
  text "1" at 97.79,-10.502 h10.16 r180
Bottom Solder:
  rectangle: 0,-50.165 10.16,-31.75
  rectangle: 0.635,31.75 8.89,50.165
  rectangle: 0.635,35.56 8.89,38.1
  lines w1.27: 0.635,-34.925 0.635,34.925
  lines w6.35: 3.175,-47.625 433.705,-47.625 433.705,47.625 3.175,47.625
Mechanical 1:
  circle w0.254: c0,0 r1.27
  rectangle: 373.38,-67.31 388.62,-62.23
  rectangle: 411.48,-67.31 421.64,-62.23
  rectangle: 449.58,-67.31 459.74,-62.23
  rectangle: 365.76,-65.405 467.36,-62.23
  rectangle: 160.02,-67.31 175.26,-62.23
  rectangle: 198.12,-67.31 208.28,-62.23
  rectangle: 236.22,-67.31 246.38,-62.23
  rectangle: 45.72,-65.405 147.32,-62.23
  rectangle: 129.54,-67.31 139.7,-62.23
  rectangle: 91.44,-67.31 101.6,-62.23
  rectangle: 53.34,-67.31 68.58,-62.23
  rectangle: 266.7,-67.31 281.94,-62.23
  rectangle: 304.8,-67.31 314.96,-62.23
  rectangle: 342.9,-67.31 353.06,-62.23
  rectangle: 259.08,-65.405 360.68,-62.23
  rectangle: 365.76,57.15 467.36,60.325
  rectangle: 373.38,57.15 383.54,62.23
  rectangle: 411.48,57.15 421.64,62.23
  rectangle: 444.5,57.15 459.74,62.23
  rectangle: 337.82,57.15 353.06,62.23
  rectangle: 304.8,57.15 314.96,62.23
  rectangle: 266.7,57.15 276.86,62.23
  rectangle: 259.08,57.15 360.68,60.325
  rectangle: 152.4,57.15 254,60.325
  rectangle: 160.02,57.15 170.18,62.23
  rectangle: 198.12,57.15 208.28,62.23
  rectangle: 231.14,57.15 246.38,62.23
  rectangle: 124.46,57.15 139.7,62.23
  rectangle: 91.44,57.15 101.6,62.23
  rectangle: 53.34,57.15 63.5,62.23
  rectangle: 45.72,57.15 147.32,60.325
  rectangle: 152.4,-65.405 254,-62.23
  lines w0.203: 111.125,-78.74 111.125,60.96 ; 217.805,-76.2 217.805,68.58 ; 431.165,-68.58 431.165,57.15 ; 416.56,-68.58 416.56,-36.83 416.56,-68.58
  lines w0.254: -3.81,0 3.175,0 ; 437.515,-58.42 437.515,-50.165 ; 437.515,50.165 437.515,64.135
  lines w0.305: 437.388,-50.292 458.978,-50.292 ; 437.388,50.038 460.248,50.038
  text "Q I" at 88.9,58.42 h4.06
  text "Q I" at 198.12,55.88 h4.06
  text "Q I" at 414.02,55.88 h4.06
  text "Q I" at 304.8,53.34 h5.08
  text "0.8mm" at 6.3,14.2 h1
  text "I Q" at 91.44,-58.42 h4.06
  text "I Q" at 195.58,-58.42 h4.06
  text "I Q" at 302.26,-58.42 h4.06
Mechanical 2:
  lines w0.152: 58.42,-43.18 58.42,42.545
  lines w0.203: 50.8,-53.34 50.8,53.34
  lines w0.254: 27.94,-47.625 29.21,-47.625 ; 28.575,-48.26 28.575,-46.99 ; 75.565,-47.625 76.835,-47.625 ; 76.2,-48.26 76.2,-46.99 ; 53.34,-52.07 68.58,-52.07 68.58,-43.18 53.34,-43.18 53.34,-52.07 ; 53.34,43.18 63.5,43.18 63.5,52.07 53.34,52.07 53.34,43.18
  text "Samtec SSW-104-02-L-D-RA" at 55.88,73.66 h3.81
  text "E:\__PROJECT\_PIERREFLAMENT\__LERA4P\ANA_BACK\GERBER\" at 12.7,66.04 h3.81
  text "ANA-SMT1.DSN" at 212.725,66.04 h3.81
  text "M-3.5 MOUNTING HOLES (3.85mm) 03/16/2017)" at 263.525,66.04 h5.08
  text "<<== L.O. BOARD" at 50.8,53.34 h4.57
  text "VHDCI-SMT" at -19.304,47.117 h10 r270
  text "DIGIKEY   WM7304-ND" at -5.715,37.465 h3.81 r270
  text "Q8" at 45.72,18.415 h1.02
  text "I8" at 45.72,15.875 h1.02
  text "Q7" at 45.72,13.335 h1.02
  text "A31" at 10.795,12.7 h1.02
  text "I7" at 45.72,10.795 h1.02
  text "Q6" at 45.72,8.255 h1.02
  text "A25" at 10.16,7.62 h1.02
  text "I6" at 45.72,5.715 h1.02
  text "Q5" at 45.72,3.175 h1.02
  text "I5" at 45.72,0.635 h1.02
  text "Q4" at 45.72,-1.905 h1.02
  text "I4" at 45.72,-4.445 h1.02
  text "Q3" at 45.72,-6.985 h1.02
  text "A8" at 10.795,-8.89 h1.02
  text "I3" at 45.72,-9.525 h1.02
  text "Q2" at 45.72,-12.065 h1.02
  text "A1" at 10.795,-13.335 h1.02
  text "I2" at 45.72,-14.605 h1.02
  text "Q1" at 45.72,-17.145 h1.02
  text "I1" at 45.72,-19.685 h1.02
  text "1125mil,-1875mil" at 19.685,-53.34 h1.52
  text "3000mil,-1875mil" at 67.31,-53.34 h1.52
  text "REV 09/09/2016" at 58.42,-58.42 h3.81
  text "GERBER 09/09/2016" at 117.475,-58.42 h3.81
  text "DRC 09/09/2016" at 194.945,-58.42 h3.81
  text "ANA-BP10.NET" at 250.825,-58.42 h3.81
  text "PNP 09/09/2016" at 57.785,-73.025 h3.81
  text "DRL 09/09/2016" at 116.84,-73.025 h3.81
  text "XLN 09/09/2016" at 173.99,-73.025 h3.81
  text "SAVE GROUND FILLS" at 249.555,-76.835 h10.16
  text "MEXICO PRODUCTION" at 66.675,-100.33 h19.05
Mechanical 5:
  lines w0.127: 299.672,-237.813 299.672,-229.133 ; 338.78,-222.308 456.082,-222.308 ; 338.78,-215.483 456.082,-215.483 ; 338.78,-204.393 456.082,-204.393 ; 338.78,-200.127 456.082,-200.127 ; 338.78,-195.861 456.082,-195.861 ; 338.78,-191.596 456.082,-191.596 ; 362.155,-208.658 362.155,-187.33 ; 379.653,-229.133 379.653,-208.658 ; 419.851,-208.658 419.851,-187.33 ; 438.873,-208.658 438.873,-187.33 ; 456.082,-187.33 299.672,-187.33 ; 299.672,-229.133 299.672,-187.33 ; 299.672,-229.133 338.78,-229.133 ; 299.672,-229.133 456.082,-229.133 ; 299.672,-187.33 338.78,-187.33 ; 338.78,-229.133 338.78,-208.658 ; 338.78,-229.133 456.082,-229.133 ; 338.78,-229.133 338.78,-187.33 ; 338.78,-229.133 338.78,-187.33 ; 338.78,-208.658 456.082,-208.658 ; 338.78,-208.658 456.082,-208.658 ; 438.015,-229.133 438.015,-215.483 ; 438.015,-229.133 456.082,-229.133 ; 438.015,-229.133 438.015,-215.483 ; 438.015,-222.308 438.015,-215.483 ; 438.015,-222.308 456.082,-222.308 ; 438.015,-222.308 438.015,-215.483 ; 438.015,-215.483 456.082,-215.483 ; 438.015,-215.483 456.082,-215.483 ; 456.082,-229.133 456.082,-208.658 ; 456.082,-229.133 456.082,-215.483 ; 456.082,-222.308 456.082,-215.483
  lines w0.5: -27.745,-237.802 -27.745,145.073 456.092,145.073 456.092,-237.802 299.692,-237.802 -27.745,-237.802
  text "Radio / Oceanography / Laboratory" at 305.619,-201.92 h4
  text "Indice" at 342.841,-207.248 h1.76
  text "Modification" at 381.81,-207.248 h1.76
  text "Date" at 425.484,-207.248 h1.76
  text "Dessine par" at 441.038,-207.331 h1.5
  text "Edition" at 339.75,-213.26 h1.76
  text ":" at 359.689,-213.26 h1.76
  text "CARTE ANNA435-2021" at 383.492,-213.902 h1.8
  text "Dessinateur" at 339.75,-219.271 h1.76
  text "Folio" at 438.89,-219.271 h1.8
  text ":" at 359.689,-219.292 h1.76
  text ":" at 447.359,-219.292 h1.76
  text "1/1" at 449.736,-219.668 h1.76
  text "RONVEL" at 362.757,-219.783 h1.95
  text ":" at 359.689,-225.885 h1.76
  text "Date" at 339.75,-225.936 h1.76
  text "Ind" at 438.89,-225.936 h1.95
  text "03-04-21" at 361.792,-226.902 h1.8
Mechanical 7:
  text "PLAN DE CABLAGE" at 387.492,-220.402 h4
Mechanical 9:
  text "PLAN DE PERCAGE" at 393.092,-220.302 h4
Drill Drawing:
  circle w0.254: c35.737,-106.219 r0.593
  circle w0.254: c35.737,-106.219 r0.988
  circle w0.254: c35.737,-115.113 r0.988
  lines w0.254: 34.749,-132.901 35.737,-133.89 36.725,-132.901 35.737,-131.913 34.749,-132.901 ; 34.749,-128.948 35.243,-128.948 35.737,-129.443 36.231,-128.948 36.725,-128.948 36.231,-128.454 36.725,-127.96 36.231,-127.96 35.737,-127.466 35.243,-127.96 34.749,-127.96 35.243,-128.454 34.749,-128.948 ; 34.749,-123.019 36.725,-123.019 35.737,-124.996 34.749,-123.019 ; 34.749,-118.572 36.725,-118.572 35.737,-120.549 34.749,-118.572 ; 34.749,-111.655 36.725,-111.655 36.725,-109.678 34.749,-109.678 34.749,-111.655 ; 34.749,-102.266 35.243,-102.266 35.243,-102.761 36.231,-102.761 36.231,-102.266 36.725,-102.266 36.725,-101.278 36.231,-101.278 36.231,-100.784 35.243,-100.784 35.243,-101.278 34.749,-101.278 34.749,-102.266 ; 35.144,-118.967 36.33,-118.967 35.737,-120.153 35.144,-118.967 ; 35.144,-111.259 36.33,-111.259 36.33,-110.073 35.144,-110.073 35.144,-111.259
  lines w0.381: 32.989,-135.224 352.073,-135.224 ; 32.989,-99.648 352.073,-99.648 ; 49.185,-139.671 49.185,-95.201 ; 68.365,-139.671 68.365,-95.201 ; 102.66,-139.671 102.66,-95.201 ; 117.522,-139.671 117.522,-95.201 ; 139.141,-139.671 139.141,-95.201 ; 183.513,-139.671 183.513,-95.201 ; 200.864,-139.671 200.864,-95.201 ; 222.839,-139.671 222.839,-95.201 ; 246.761,-139.671 246.761,-95.201 ; 271.936,-139.671 271.936,-95.201 ; 311.337,-139.671 311.337,-95.201 ; 32.989,-139.671 352.073,-139.671 352.073,-95.201 32.989,-95.201 32.989,-139.671
  text "Symbol" at 35.657,-98.314 h2.13
  text "Count" at 50.519,-98.314 h2.13
  text "Hole Size" at 69.699,-98.314 h2.13
  text "Plated" at 103.995,-98.314 h2.13
  text "Hole Type" at 118.856,-98.314 h2.13
  text "Drill Layer Pair" at 140.475,-98.314 h2.13
  text "Via/Pad" at 184.847,-98.314 h2.13
  text "Pad Shape" at 202.198,-98.314 h2.13
  text "Template" at 224.173,-98.314 h2.13
  text "Description" at 248.095,-98.314 h2.13
  text "Hole Tolerance (+)" at 273.27,-98.314 h2.13
  text "Hole Tolerance (-)" at 312.671,-98.314 h2.13
  text "2" at 50.519,-102.761 h1.78
  text "1,200mm (47,24mil)" at 69.699,-102.761 h1.78
  text "PTH" at 103.995,-102.761 h1.78
  text "Round" at 118.856,-102.761 h1.78
  text "Top Layer - Bottom Layer" at 140.475,-102.761 h1.78
  text "Pad" at 184.847,-102.761 h1.78
  text "Rounded" at 202.198,-102.761 h1.78
  text "c225h120" at 224.173,-102.761 h1.78
  text "2" at 50.519,-107.208 h1.78
  text "1,750mm (68,90mil)" at 69.699,-107.208 h1.78
  text "PTH" at 103.995,-107.208 h1.78
  text "Round" at 118.856,-107.208 h1.78
  text "Top Layer - Bottom Layer" at 140.475,-107.208 h1.78
  text "Via" at 184.847,-107.208 h1.78
  text "Rounded" at 202.198,-107.208 h1.78
  text "v240h175" at 224.173,-107.208 h1.78
  text "4" at 50.519,-111.655 h1.78
  text "2,440mm (96,06mil)" at 69.699,-111.655 h1.78
  text "PTH" at 103.995,-111.655 h1.78
  text "Round" at 118.856,-111.655 h1.78
  text "Top Layer - Bottom Layer" at 140.475,-111.655 h1.78
  text "Via" at 184.847,-111.655 h1.78
  text "Rounded" at 202.198,-111.655 h1.78
  text "v324h244" at 224.173,-111.655 h1.78
  text "12" at 50.519,-116.102 h1.78
  text "3,850mm (151,58mil)" at 69.699,-116.102 h1.78
  text "PTH" at 103.995,-116.102 h1.78
  text "Round" at 118.856,-116.102 h1.78
  text "Top Layer - Bottom Layer" at 140.475,-116.102 h1.78
  text "Via" at 184.847,-116.102 h1.78
  text "Rounded" at 202.198,-116.102 h1.78
  text "v508h385m473" at 224.173,-116.102 h1.78
  text "15" at 50.519,-120.549 h1.78
  text "0,700mm (27,56mil)" at 69.699,-120.549 h1.78
  text "PTH" at 103.995,-120.549 h1.78
  text "Round" at 118.856,-120.549 h1.78
  text "Top Layer - Bottom Layer" at 140.475,-120.549 h1.78
  text "Via" at 184.847,-120.549 h1.78
  text "Rounded" at 202.198,-120.549 h1.78
  text "v110h70m55" at 224.173,-120.549 h1.78
  text "64" at 50.519,-124.996 h1.78
  text "0,914mm (36,00mil)" at 69.699,-124.996 h1.78
  text "PTH" at 103.995,-124.996 h1.78
  text "Round" at 118.856,-124.996 h1.78
  text "Top Layer - Bottom Layer" at 140.475,-124.996 h1.78
  text "Pad" at 184.847,-124.996 h1.78
  text "(Mixed)" at 202.198,-124.996 h1.78
  text "(Mixed)" at 224.173,-124.996 h1.78
  text "64" at 50.519,-129.443 h1.78
  text "0,965mm (38,00mil)" at 69.699,-129.443 h1.78
  text "PTH" at 103.995,-129.443 h1.78
  text "Round" at 118.856,-129.443 h1.78
  text "Top Layer - Bottom Layer" at 140.475,-129.443 h1.78
  text "Pad" at 184.847,-129.443 h1.78
  text "(Mixed)" at 202.198,-129.443 h1.78
  text "(Mixed)" at 224.173,-129.443 h1.78
  text "1209" at 50.519,-133.89 h1.78
  text "0,300mm (11,81mil)" at 69.699,-133.89 h1.78
  text "PTH" at 103.995,-133.89 h1.78
  text "Round" at 118.856,-133.89 h1.78
  text "Top Layer - Bottom Layer" at 140.475,-133.89 h1.78
  text "Via" at 184.847,-133.89 h1.78
  text "Rounded" at 202.198,-133.89 h1.78
  text "v70h30m35" at 224.173,-133.89 h1.78
  text "1372 Total" at 50.519,-138.337 h1.78
  text "MATIERE FR4 16/10eme / CUIVRE 35 Microns 2 faces / TECHNO DOUBLE FACE / VERNIS SELECTIF VERT 2 FACES / SERIGRAPHIE BLANCHE FACE TOP / FINITION NiAu" at 61.155,-204.177 h2.5

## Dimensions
0,-50.8 to 436.88,-50.8 on Drill Drawing
0,-50.8 to 0,50.8 on Drill Drawing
